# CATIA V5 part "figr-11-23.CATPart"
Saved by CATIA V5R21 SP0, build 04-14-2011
Part number: Part1
Bounding box of the stored display mesh (mm): x -89.703 to 75.958, y -127.286 to 108.862, z -26.487 to 19.815
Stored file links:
  D:\CATIA V5R21 E-RESOURCES\CATIA-V5R21\catia-v5r21-prt\c11-catia-v5r21-prt\c11-catia-v5r21-figr-11-23.CATPart
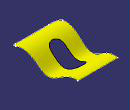
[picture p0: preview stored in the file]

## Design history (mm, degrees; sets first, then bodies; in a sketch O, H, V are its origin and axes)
Set1
  Extrude1: Element1 Sketch3, Lim1 86, Lim2 94, Direction yz-plane
  Sketch1 on xy-plane, origin (0, 0, 0), H (1, 0, 0), V (0, 1, 0)
    line L1 (64.3059, 108.8616) -> (75.9293, -106.0218)
    arc A1 centre (55.7837, -107.1115) radius 20.175 from (75.9293, -106.0218) to (55.7837, -127.2865) cw
    line L2 (55.7837, -127.2865) -> (-64.7868, -127.2865)
    arc A2 centre (-64.7868, -102.3613) radius 24.9252 from (-64.7868, -127.2865) to (-89.6873, -101.2501) cw
    line L3 (-89.6873, -101.2501) -> (-80.3115, 108.8616)
    line L4 (-80.3115, 108.8616) -> (64.3059, 108.8616)
    tangency: A1 L1, A2 L2, A2 L3, A1 L2
    horizontal: L2 H, L4 H
  Extrude2: Element1 Sketch1, Lim1 86, Lim2 94, Direction xy-plane
  Split1: ToCut Extrude1, Cutting Extrude2
  Sketch2 on xy-plane, origin (0, 0, 0), H (1, 0, 0), V (0, 1, 0)
    construction line L1 (-11.3849, 28.4134) -> (-11.3849, -36.9379)
    line L2 (12.8382, 28.4134) -> (12.8382, -36.9379)
    line L3 (-35.608, -36.9379) -> (-35.608, 28.4134)
    arc A1 centre (-11.3849, -36.9379) radius 24.2231 from (12.8382, -36.9379) to (-35.608, -36.9379) cw
    arc A2 centre (-11.3849, 28.4134) radius 24.2231 from (-35.608, 28.4134) to (12.8382, 28.4134) cw
    vertical: L1 V
    tangency: A1 L2, A2 L2, A1 L3, A2 L3
    parallelism: L1 L2
  Extrude3: Element1 Sketch2, Lim1 86, Lim2 94, Direction xy-plane
  Split2: ToCut Split1, Cutting Extrude3
  Boundary1: Boundary edge of Split2, Support Split2
Body1 (main body)
  Sketch3 on yz-plane, origin (0, 0, 0), H (0, 1, 0), V (0, 0, 1)
    spline S1 through (-130.9721, 0) (-85.5087, 19.8151) (-38.0512, 0) (0, -25.6483) (60.0541, -1.7202) (134.7951, -4.3868)
    point P1 (-130.9721, 0)
    point P2 (-38.0512, 0)
    point P3 (0, -25.6483)
    coincidence: P1 H, P2 H, P3 V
